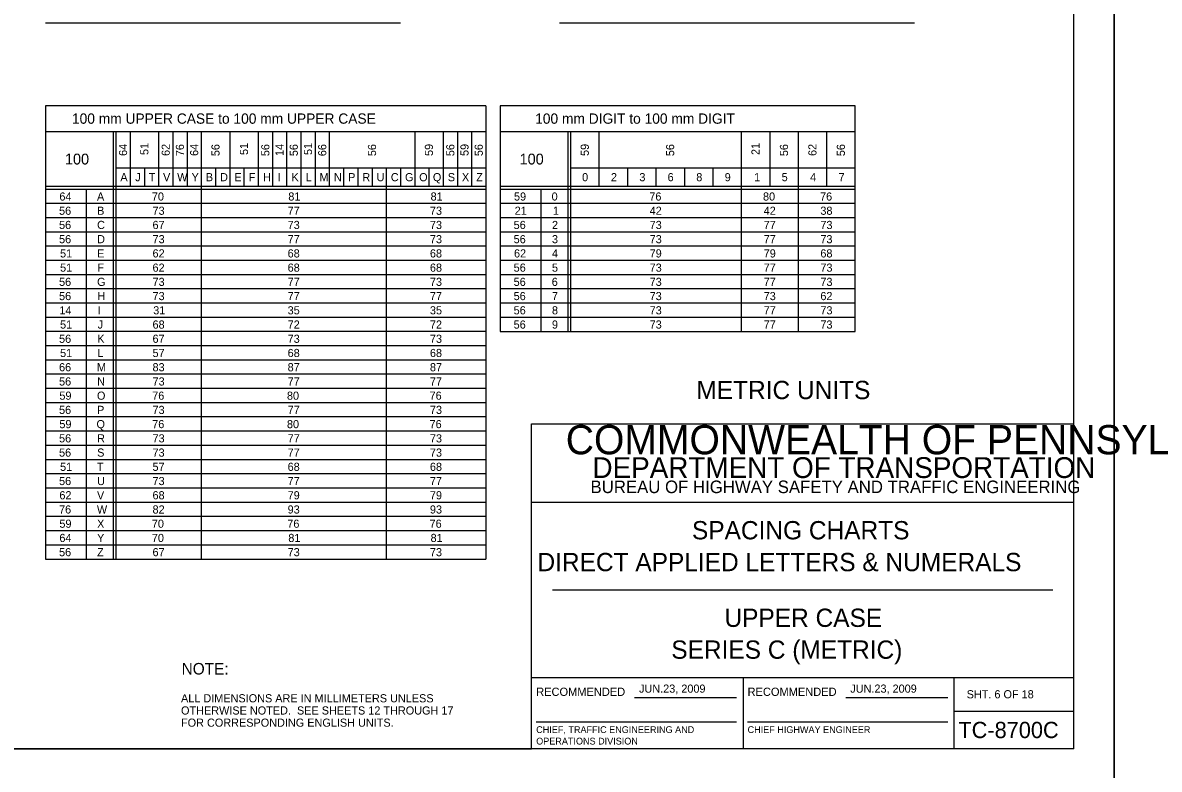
# Model space of a CAD drawing. Extents: x 637580 to 641849, y 297270 to 299646.
# Drawn here: x 638859.5 to 639278.9, y 298465.1 to 298740.6 of the extents above; entities that cross this region are included whole.
import ezdxf

# ---------------------------------------------------------------- set-up
doc = ezdxf.new("R2010")
doc.units = 0
for name, color, linetype in [('1', 7, 'Continuous'), ('2', 7, 'Continuous'), ('XCS-GRID-HVGL', 7, 'Continuous')]:
    doc.layers.add(name, color=color, linetype=linetype)

msp = doc.modelspace()

# ---------------------------------------------------------------- linework, layer by layer
at = {"layer": '1'}
for p, q in [((639247.31, 298472.63), (639247.31, 299036.63)), ((639047.31, 298472.63), (639047.31, 298592.63)), ((639047.31, 298592.63), (639247.31, 298592.63)), ((639247.31, 298563.63), (639047.31, 298563.63)), ((639055.06, 298531.31), (639239.56, 298531.31)), ((639047.31, 298499), (639247.31, 298499)), ((639125.31, 298499), (639125.31, 298472.63)), ((639203.19, 298472.63), (639203.19, 298499)), ((639085.24, 298491.57), (639122.87, 298491.57)), ((639163.24, 298491.57), (639200.87, 298491.57)), ((639203.19, 298486.63), (639247.31, 298486.63)), ((639048.99, 298482.68), (639122.87, 298482.68)), ((639126.99, 298482.68), (639200.87, 298482.68)), ((639247.31, 298472.63), (638461.31, 298472.63)), ((638461.31, 298472.63), (639047.31, 298472.63))]:
    msp.add_line(p, q, dxfattribs=at)
at = {"layer": '2'}
for p, q in [((638867.91, 298740.63), (638998.91, 298740.63)), ((639057.61, 298740.63), (639188.61, 298740.63)), ((639030.41, 298710), (638867.91, 298710)), ((638867.91, 298710), (638867.91, 298542.63)), ((639030.41, 298710), (639030.41, 298542.63)), ((639166.66, 298710), (639035.66, 298710)), ((639035.66, 298710), (639035.66, 298626.63)), ((639166.66, 298626.63), (639166.66, 298710)), ((638867.91, 298700.5), (639030.41, 298700.5)), ((638892.91, 298700.5), (638892.91, 298542.63)), ((638893.91, 298700.5), (638893.91, 298542.63)), ((638899.16, 298700.5), (638899.16, 298680.13)), ((638909.66, 298700.5), (638909.66, 298680.13)), ((638914.91, 298700.5), (638914.91, 298680.13)), ((638920.16, 298700.5), (638920.16, 298680.13)), ((638925.41, 298700.5), (638925.41, 298542.63)), ((638935.91, 298700.5), (638935.91, 298680.13)), ((638946.41, 298700.5), (638946.41, 298680.13)), ((638951.66, 298700.5), (638951.66, 298680.13)), ((638956.91, 298700.5), (638956.91, 298680.13)), ((638962.16, 298700.5), (638962.16, 298680.13)), ((638967.41, 298700.5), (638967.41, 298680.13)), ((638972.66, 298700.5), (638972.66, 298680.13)), ((639004.16, 298700.5), (639004.16, 298680.13)), ((639014.66, 298700.5), (639014.66, 298680.13)), ((639019.91, 298700.5), (639019.91, 298680.13)), ((639025.16, 298700.5), (639025.16, 298680.13)), ((639035.66, 298700.5), (639166.66, 298700.5)), ((639060.66, 298700.5), (639060.66, 298626.63)), ((639061.66, 298700.5), (639061.66, 298626.63)), ((639072.16, 298700.5), (639072.16, 298680.13)), ((639124.66, 298700.5), (639124.66, 298626.63)), ((639135.16, 298700.5), (639135.16, 298680.13)), ((639145.66, 298700.5), (639145.66, 298626.63)), ((639156.16, 298700.5), (639156.16, 298680.13)), ((638893.91, 298687.13), (639030.41, 298687.13)), ((638904.41, 298687.13), (638904.41, 298680.13)), ((638930.66, 298687.13), (638930.66, 298680.13)), ((638941.16, 298687.13), (638941.16, 298680.13)), ((638977.91, 298687.13), (638977.91, 298680.13)), ((638983.16, 298687.13), (638983.16, 298680.13)), ((638988.41, 298687.13), (638988.41, 298680.13)), ((638988.41, 298687.13), (638988.41, 298680.13)), ((638993.66, 298687.13), (638993.66, 298542.63)), ((638998.91, 298687.13), (638998.91, 298680.13)), ((639009.41, 298687.13), (639009.41, 298680.13)), ((639061.66, 298687.13), (639166.66, 298687.13)), ((639082.66, 298687.13), (639082.66, 298680.13)), ((639093.16, 298687.13), (639093.16, 298680.13)), ((639103.66, 298687.13), (639103.66, 298680.13)), ((639114.16, 298687.13), (639114.16, 298680.13)), ((639030.41, 298680.13), (638867.91, 298680.13)), ((639030.41, 298679.13), (638867.91, 298679.13)), ((638882.91, 298679.13), (638882.91, 298542.63)), ((639166.66, 298680.13), (639035.66, 298680.13)), ((639166.66, 298679.13), (639035.66, 298679.13)), ((639050.66, 298679.13), (639050.66, 298626.63)), ((639030.41, 298673.88), (638867.91, 298673.88)), ((639166.66, 298673.88), (639035.66, 298673.88)), ((639030.41, 298668.63), (638867.91, 298668.63)), ((639166.66, 298668.63), (639035.66, 298668.63)), ((639030.41, 298663.38), (638867.91, 298663.38)), ((639166.66, 298663.38), (639035.66, 298663.38)), ((639030.41, 298658.13), (638867.91, 298658.13)), ((639166.66, 298658.13), (639035.66, 298658.13)), ((639030.41, 298652.88), (638867.91, 298652.88)), ((639166.66, 298652.88), (639035.66, 298652.88)), ((639030.41, 298647.63), (638867.91, 298647.63)), ((639166.66, 298647.63), (639035.66, 298647.63)), ((639030.41, 298642.38), (638867.91, 298642.38)), ((639166.66, 298642.38), (639035.66, 298642.38)), ((639030.41, 298637.13), (638867.91, 298637.13)), ((639166.66, 298637.13), (639035.66, 298637.13)), ((639030.41, 298631.88), (638867.91, 298631.88)), ((639166.66, 298631.88), (639035.66, 298631.88)), ((639030.41, 298626.63), (638867.91, 298626.63)), ((639035.66, 298626.63), (639166.66, 298626.63)), ((639030.41, 298621.38), (638867.91, 298621.38)), ((639030.41, 298616.13), (638867.91, 298616.13)), ((639030.41, 298610.88), (638867.91, 298610.88)), ((639030.41, 298605.63), (638867.91, 298605.63)), ((639030.41, 298600.38), (638867.91, 298600.38)), ((639030.41, 298595.13), (638867.91, 298595.13)), ((639030.41, 298589.88), (638867.91, 298589.88)), ((639030.41, 298584.63), (638867.91, 298584.63)), ((639030.41, 298579.38), (638867.91, 298579.38)), ((639030.41, 298574.13), (638867.91, 298574.13)), ((639030.41, 298568.88), (638867.91, 298568.88)), ((639030.41, 298563.63), (638867.91, 298563.63)), ((639030.41, 298558.38), (638867.91, 298558.38)), ((639030.41, 298553.13), (638867.91, 298553.13)), ((639030.41, 298547.88), (638867.91, 298547.88)), ((638867.91, 298542.63), (638867.91, 298542.63)), ((638867.91, 298542.63), (639030.41, 298542.63))]:
    msp.add_line(p, q, dxfattribs=at)
at = {"layer": 'XCS-GRID-HVGL'}
for points in [[(638421.31, 299051.63), (639262.31, 299051.63), (639262.31, 298457.63), (638421.31, 298457.63)], [(639262.31, 299051.63), (640103.31, 299051.63), (640103.31, 298457.63), (639262.31, 298457.63)]]:
    msp.add_lwpolyline(points, close=True, dxfattribs=at)

# ---------------------------------------------------------------- texts
at = {"layer": '1'}
for s, height, p in [('COMMONWEALTH OF PENNSYLVANIA', 10.7828, (639059.9, 298581.36)), ('DEPARTMENT OF TRANSPORTATION', 7.6837, (639069.76, 298572.61)), ('BUREAU OF HIGHWAY SAFETY AND TRAFFIC ENGINEERING', 4.6253, (639069.04, 298567.04)), ('SPACING CHARTS', 6.75, (639106.47, 298549.97)), ('DIRECT APPLIED LETTERS & NUMERALS', 6.75, (639049.47, 298538.22)), ('UPPER CASE', 6.75, (639118.47, 298517.66)), ('SERIES C (METRIC)', 6.75, (639098.84, 298505.91)), ('RECOMMENDED', 3.048, (639048.99, 298492.2)), ('RECOMMENDED', 3.048, (639126.99, 298492.2)), ('SHT. 6 OF 18', 3, (639207.82, 298491.31)), ('TC-8700C', 6, (639204.77, 298476.63)), ('CHIEF, TRAFFIC ENGINEERING AND', 2.5, (639048.99, 298478.51)), ('CHIEF HIGHWAY ENGINEER', 2.5, (639126.99, 298478.51)), ('OPERATIONS DIVISION', 2.5, (639048.99, 298474.26))]:
    msp.add_text(s, height=height, dxfattribs=at).set_placement(p)
at = {"layer": '2'}
for s, height, p in [('100 mm UPPER CASE to 100 mm UPPER CASE', 3.8, (638877.7, 298703.35)), ('100 mm DIGIT to 100 mm DIGIT', 3.8, (639048.61, 298703.35)), ('100', 4, (638875.1, 298688.31)), ('100', 4, (639042.85, 298688.31)), ('A', 3, (638895.56, 298682.13)), ('J', 3, (638901.04, 298682.13)), ('T', 3, (638906.04, 298682.13)), ('V', 3, (638911.31, 298682.13)), ('W', 3, (638916.53, 298682.13)), ('Y', 3, (638921.84, 298682.13)), ('B', 3, (638927.1, 298682.13)), ('D', 3, (638932.35, 298682.13)), ('E', 3, (638937.62, 298682.13)), ('F', 3, (638942.92, 298682.13)), ('H', 3, (638948.19, 298682.13)), ('I', 3, (638953.6, 298682.13)), ('K', 3, (638958.69, 298682.13)), ('L', 3, (638963.94, 298682.13)), ('M', 3, (638969.03, 298682.13)), ('N', 3, (638974.35, 298682.13)), ('P', 3, (638979.6, 298682.13)), ('R', 3, (638984.85, 298682.13)), ('U', 3, (638990.09, 298682.13)), ('C', 3, (638995.35, 298682.13)), ('G', 3, (639000.6, 298682.13)), ('O', 3, (639005.81, 298682.13)), ('Q', 3, (639010.88, 298682.13)), ('S', 3, (639016.37, 298682.13)), ('X', 3, (639021.59, 298682.13)), ('Z', 3, (639026.85, 298682.13)), ('0', 3, (639065.93, 298682.13)), ('2', 3, (639076.56, 298682.13)), ('3', 3, (639087.06, 298682.13)), ('6', 3, (639097.48, 298682.13)), ('8', 3, (639108.06, 298682.13)), ('9', 3, (639118.55, 298682.13)), ('1', 3, (639129.4, 298682.13)), ('5', 3, (639139.56, 298682.13)), ('4', 3, (639150.06, 298682.13)), ('7', 3, (639160.56, 298682.13)), ('64', 3, (638873.06, 298675)), ('A', 3, (638886.93, 298675)), ('70', 3, (638907.18, 298675)), ('81', 3, (638957.53, 298675)), ('81', 3, (639010.03, 298675)), ('59', 3, (639040.8, 298675)), ('0', 3, (639054.68, 298675)), ('76', 3, (639090.73, 298675)), ('80', 3, (639132.68, 298675)), ('76', 3, (639153.73, 298675)), ('56', 3, (638872.94, 298669.75)), ('B', 3, (638886.98, 298669.75)), ('73', 3, (638907.43, 298669.75)), ('77', 3, (638957.28, 298669.75)), ('73', 3, (639009.78, 298669.75)), ('21', 3, (639041.05, 298669.75)), ('1', 3, (639055.15, 298669.75)), ('42', 3, (639090.85, 298669.75)), ('42', 3, (639132.93, 298669.75)), ('38', 3, (639153.85, 298669.75)), ('56', 3, (638872.94, 298664.5)), ('C', 3, (638886.98, 298664.5)), ('67', 3, (638907.43, 298664.5)), ('73', 3, (638957.28, 298664.5)), ('73', 3, (639009.78, 298664.5)), ('56', 3, (639040.67, 298664.5)), ('2', 3, (639054.81, 298664.5)), ('73', 3, (639090.85, 298664.5)), ('77', 3, (639132.93, 298664.5)), ('73', 3, (639153.85, 298664.5)), ('56', 3, (638872.94, 298659.25)), ('D', 3, (638886.98, 298659.25)), ('73', 3, (638907.43, 298659.25)), ('77', 3, (638957.28, 298659.25)), ('73', 3, (639009.78, 298659.25)), ('56', 3, (639040.67, 298659.25)), ('3', 3, (639054.81, 298659.25)), ('73', 3, (639090.85, 298659.25)), ('77', 3, (639132.93, 298659.25)), ('73', 3, (639153.85, 298659.25)), ('51', 3, (638873.31, 298654)), ('E', 3, (638886.99, 298654)), ('62', 3, (638907.43, 298654)), ('68', 3, (638957.28, 298654)), ('68', 3, (639009.78, 298654)), ('62', 3, (639040.8, 298654)), ('4', 3, (639054.81, 298654)), ('79', 3, (639090.85, 298654)), ('79', 3, (639132.93, 298654)), ('68', 3, (639153.85, 298654)), ('51', 3, (638873.31, 298648.75)), ('F', 3, (638887.05, 298648.75)), ('62', 3, (638907.43, 298648.75)), ('68', 3, (638957.28, 298648.75)), ('68', 3, (639009.78, 298648.75)), ('56', 3, (639040.67, 298648.75)), ('5', 3, (639054.81, 298648.75)), ('73', 3, (639090.85, 298648.75)), ('77', 3, (639132.93, 298648.75)), ('73', 3, (639153.85, 298648.75)), ('56', 3, (638872.94, 298643.5)), ('G', 3, (638886.98, 298643.5)), ('73', 3, (638907.43, 298643.5)), ('77', 3, (638957.28, 298643.5)), ('73', 3, (639009.78, 298643.5)), ('56', 3, (639040.67, 298643.5)), ('6', 3, (639054.73, 298643.5)), ('73', 3, (639090.85, 298643.5)), ('77', 3, (639132.93, 298643.5)), ('73', 3, (639153.85, 298643.5)), ('56', 3, (638872.94, 298638.25)), ('H', 3, (638887.06, 298638.25)), ('73', 3, (638907.43, 298638.25)), ('77', 3, (638957.28, 298638.25)), ('77', 3, (639009.78, 298638.25)), ('56', 3, (639040.67, 298638.25)), ('7', 3, (639054.81, 298638.25)), ('73', 3, (639090.85, 298638.25)), ('73', 3, (639132.93, 298638.25)), ('62', 3, (639153.85, 298638.25)), ('14', 3, (638873.06, 298633)), ('I', 3, (638887.23, 298633)), ('31', 3, (638907.68, 298633)), ('35', 3, (638957.28, 298633)), ('35', 3, (639009.78, 298633)), ('56', 3, (639040.67, 298633)), ('8', 3, (639054.81, 298633)), ('73', 3, (639090.85, 298633)), ('77', 3, (639132.93, 298633)), ('73', 3, (639153.85, 298633)), ('51', 3, (638873.31, 298627.75)), ('J', 3, (638887.17, 298627.75)), ('68', 3, (638907.43, 298627.75)), ('72', 3, (638957.28, 298627.75)), ('72', 3, (639009.78, 298627.75)), ('56', 3, (639040.67, 298627.75)), ('9', 3, (639054.8, 298627.75)), ('73', 3, (639090.85, 298627.75)), ('77', 3, (639132.93, 298627.75)), ('73', 3, (639153.85, 298627.75)), ('56', 3, (638872.94, 298622.5)), ('K', 3, (638887.06, 298622.5)), ('67', 3, (638907.43, 298622.5)), ('73', 3, (638957.28, 298622.5)), ('73', 3, (639009.78, 298622.5)), ('51', 3, (638873.31, 298617.25)), ('L', 3, (638887.06, 298617.25)), ('57', 3, (638907.43, 298617.25)), ('68', 3, (638957.28, 298617.25)), ('68', 3, (639009.78, 298617.25)), ('66', 3, (638872.94, 298612)), ('M', 3, (638886.91, 298612)), ('83', 3, (638907.43, 298612)), ('87', 3, (638957.28, 298612)), ('87', 3, (639009.78, 298612)), ('56', 3, (638872.94, 298606.75)), ('N', 3, (638886.98, 298606.75)), ('73', 3, (638907.43, 298606.75)), ('77', 3, (638957.28, 298606.75)), ('77', 3, (639009.78, 298606.75)), ('METRIC UNITS', 6.75, (639108.11, 298601.72)), ('59', 3, (638873.06, 298601.5)), ('O', 3, (638886.93, 298601.5)), ('76', 3, (638907.31, 298601.5)), ('80', 3, (638957.03, 298601.5)), ('76', 3, (639009.65, 298601.5)), ('56', 3, (638872.94, 298596.25)), ('P', 3, (638886.98, 298596.25)), ('73', 3, (638907.43, 298596.25)), ('77', 3, (638957.28, 298596.25)), ('73', 3, (639009.78, 298596.25)), ('59', 3, (638873.06, 298591)), ('Q', 3, (638886.75, 298591)), ('76', 3, (638907.31, 298591)), ('80', 3, (638957.03, 298591)), ('76', 3, (639009.65, 298591)), ('56', 3, (638872.94, 298585.75)), ('R', 3, (638886.98, 298585.75)), ('73', 3, (638907.43, 298585.75)), ('77', 3, (638957.28, 298585.75)), ('73', 3, (639009.78, 298585.75)), ('56', 3, (638872.94, 298580.5)), ('S', 3, (638886.99, 298580.5)), ('73', 3, (638907.43, 298580.5)), ('77', 3, (638957.28, 298580.5)), ('73', 3, (639009.78, 298580.5)), ('51', 3, (638873.31, 298575.25)), ('T', 3, (638886.92, 298575.25)), ('57', 3, (638907.43, 298575.25)), ('68', 3, (638957.28, 298575.25)), ('68', 3, (639009.78, 298575.25)), ('56', 3, (638872.94, 298570)), ('U', 3, (638886.97, 298570)), ('73', 3, (638907.43, 298570)), ('77', 3, (638957.28, 298570)), ('77', 3, (639009.78, 298570)), ('62', 3, (638873.06, 298564.75)), ('V', 3, (638886.93, 298564.75)), ('68', 3, (638907.43, 298564.75)), ('79', 3, (638957.28, 298564.75)), ('79', 3, (639009.78, 298564.75)), ('76', 3, (638872.94, 298559.5)), ('W', 3, (638886.91, 298559.5)), ('82', 3, (638907.43, 298559.5)), ('93', 3, (638957.28, 298559.5)), ('93', 3, (639009.78, 298559.5)), ('59', 3, (638873.06, 298554.25)), ('X', 3, (638886.97, 298554.25)), ('70', 3, (638907.18, 298554.25)), ('76', 3, (638957.15, 298554.25)), ('76', 3, (639009.65, 298554.25)), ('64', 3, (638873.06, 298549)), ('Y', 3, (638886.97, 298549)), ('70', 3, (638907.18, 298549)), ('81', 3, (638957.53, 298549)), ('81', 3, (639010.03, 298549)), ('56', 3, (638872.94, 298543.75)), ('Z', 3, (638886.98, 298543.75)), ('67', 3, (638907.43, 298543.75)), ('73', 3, (638957.28, 298543.75)), ('73', 3, (639009.78, 298543.75)), ('NOTE:', 4.25, (638918.16, 298500.1)), ('JUN.23, 2009', 3, (639086.93, 298493.39)), ('ALL DIMENSIONS ARE IN MILLIMETERS UNLESS', 3, (638917.94, 298489.83)), ('OTHERWISE NOTED.  SEE SHEETS 12 THROUGH 17', 3, (638917.94, 298485.33)), ('FOR CORRESPONDING ENGLISH UNITS.', 3, (638917.94, 298480.83))]:
    msp.add_text(s, height=height, dxfattribs=at).set_placement(p)
for s, rotation, p in [('64', 90, (638898.04, 298691.46)), ('51', 90, (638905.91, 298691.81)), ('62', 90, (638913.79, 298691.46)), ('76', 90, (638919.04, 298691.38)), ('64', 90, (638924.29, 298691.46)), ('56', 90, (638932.16, 298691.38)), ('51', 90, (638942.66, 298691.81)), ('56', 90, (638950.54, 298691.38)), ('14', 90, (638955.79, 298691.46)), ('56', 90, (638961.04, 298691.38)), ('51', 90, (638966.29, 298691.81)), ('66', 90, (638971.54, 298691.38)), ('56', 90, (638989.91, 298691.38)), ('59', 90, (639010.91, 298691.45)), ('56', 90, (639018.79, 298691.38)), ('59', 90, (639024.04, 298691.45)), ('56', 90, (639029.29, 298691.38)), ('59', 90, (639068.41, 298691.45)), ('56', 90, (639099.91, 298691.38)), ('21', 90, (639131.41, 298691.81)), ('56', 90, (639141.91, 298691.38)), ('62', 90, (639152.41, 298691.46)), ('56', 90, (639162.91, 298691.38)), ('JUN.23, 2009', 360, (639164.88, 298493.39))]:
    msp.add_text(s, height=3, rotation=rotation, dxfattribs=at).set_placement(p)

doc.saveas('drawing.dxf')
